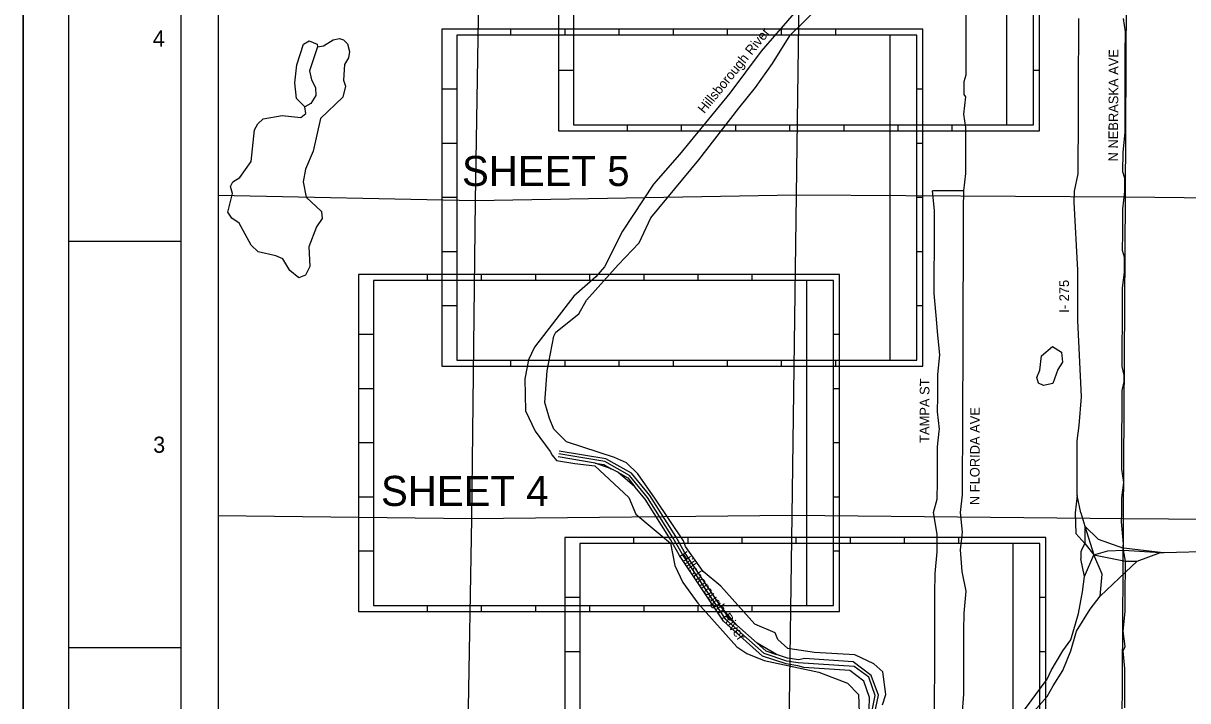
# Model space of a CAD drawing. Extents: x 492225 to 553725, y 1303773 to 1347273.
# Drawn here: x 492225 to 511586, y 1317894 to 1329150 of the extents above; entities that cross this region are included whole.
import ezdxf

# ---------------------------------------------------------------- set-up
doc = ezdxf.new("R2010")
doc.units = 0
for name, color, linetype in [('G-ANNO-TTLB', 7, 'Continuous'), ('Level 1', 7, 'Continuous'), ('Level 13', 7, 'Continuous'), ('Level 19', 7, 'Continuous'), ('Level 22', 7, 'Continuous'), ('Level 28', 7, 'Continuous'), ('Level 41', 7, 'Continuous'), ('Level 5', 7, 'Continuous'), ('Level 50', 7, 'Continuous'), ('Level 52', 7, 'Continuous'), ('Level 6', 7, 'Continuous'), ('Level 7', 7, 'Continuous')]:
    doc.layers.add(name, color=color, linetype=linetype)

msp = doc.modelspace()

# ---------------------------------------------------------------- linework, layer by layer
at = {"layer": 'G-ANNO-TTLB'}
for p, q in [((492975.069, 1346522.564), (492975.069, 1304522.564)), ((494850.069, 1305272.564), (494850.069, 1345772.564)), ((494850.069, 1325522.564), (492975.069, 1325522.564)), ((494850.069, 1318772.564), (492975.069, 1318772.564))]:
    msp.add_line(p, q, dxfattribs=at)
for points in [[(492225.069, 1303772.564), (553725.069, 1303772.564), (553725.069, 1347272.564), (492225.069, 1347272.564)], [(492225.069, 1303772.564), (553725.069, 1303772.564), (553725.069, 1347272.564), (492225.069, 1347272.564)], [(492225.069, 1347272.564), (553725.069, 1347272.564), (553725.069, 1303772.564), (492225.069, 1303772.564)]]:
    msp.add_lwpolyline(points, close=True, dxfattribs=at)
at = {"layer": 'Level 1'}
for p, q in [((508571.149, 1332863.868), (508571.149, 1327463.868)), ((499828.525, 1331625.601), (499738.271, 1326200.768)), ((505144.045, 1331549.672), (505073.326, 1326292.17)), ((510570.569, 1331572.735), (510543.414, 1326261.323)), ((500333.521, 1328952.653), (500333.521, 1329052.653)), ((501233.521, 1328952.653), (501233.521, 1329052.653)), ((502133.521, 1328952.653), (502133.521, 1329052.653)), ((503033.521, 1328952.653), (503033.521, 1329052.653)), ((503933.521, 1328952.653), (503933.521, 1329052.653)), ((504833.521, 1328952.653), (504833.521, 1329052.653)), ((505733.521, 1328952.653), (505733.521, 1329052.653)), ((506633.521, 1328952.653), (506633.521, 1323552.653)), ((501371.149, 1328363.868), (501121.149, 1328363.868)), ((509121.149, 1328363.868), (509021.149, 1328363.868)), ((499433.521, 1328052.653), (499183.521, 1328052.653)), ((507183.521, 1328052.653), (507083.521, 1328052.653)), ((502271.149, 1327363.868), (502271.149, 1327463.868)), ((503171.149, 1327363.868), (503171.149, 1327463.868)), ((504071.149, 1327363.868), (504071.149, 1327463.868)), ((504971.149, 1327363.868), (504971.149, 1327463.868)), ((505871.149, 1327363.868), (505871.149, 1327463.868)), ((506771.149, 1327363.868), (506771.149, 1327463.868)), ((507671.149, 1327363.868), (507671.149, 1327463.868)), ((499433.521, 1327152.653), (499183.521, 1327152.653)), ((507183.521, 1327152.653), (507083.521, 1327152.653)), ((499738.271, 1326200.768), (495463.793, 1326290.169)), ((499433.521, 1326252.653), (499183.521, 1326252.653)), ((499738.271, 1326200.768), (499675.349, 1320917.678)), ((505073.326, 1326292.17), (499738.271, 1326200.768)), ((505073.326, 1326292.17), (505001.79, 1320973.847)), ((510543.414, 1326261.323), (505073.326, 1326292.17)), ((507183.521, 1326252.653), (507083.521, 1326252.653)), ((510543.414, 1326261.323), (510511.962, 1320917.95)), ((515873.149, 1326207.263), (510543.414, 1326261.323)), ((499433.521, 1325352.653), (499183.521, 1325352.653)), ((507183.521, 1325352.653), (507083.521, 1325352.653)), ((498946.2, 1324877.911), (498946.2, 1324977.911)), ((499846.2, 1324877.911), (499846.2, 1324977.911)), ((500746.2, 1324877.911), (500746.2, 1324977.911)), ((501646.2, 1324877.911), (501646.2, 1324977.911)), ((502546.2, 1324877.911), (502546.2, 1324977.911)), ((503446.2, 1324877.911), (503446.2, 1324977.911)), ((504346.2, 1324877.911), (504346.2, 1324977.911)), ((505246.2, 1324877.911), (505246.2, 1319477.911)), ((499433.521, 1324452.653), (499183.521, 1324452.653)), ((507183.521, 1324452.653), (507083.521, 1324452.653)), ((498046.2, 1323977.911), (497796.2, 1323977.911)), ((505796.2, 1323977.911), (505696.2, 1323977.911)), ((500333.521, 1323452.653), (500333.521, 1323552.653)), ((501233.521, 1323452.653), (501233.521, 1323552.653)), ((502133.521, 1323452.653), (502133.521, 1323552.653)), ((503033.521, 1323452.653), (503033.521, 1323552.653)), ((503933.521, 1323452.653), (503933.521, 1323552.653)), ((504833.521, 1323452.653), (504833.521, 1323552.653)), ((505733.521, 1323452.653), (505733.521, 1323552.653)), ((498046.2, 1323077.911), (497796.2, 1323077.911)), ((505796.2, 1323077.911), (505696.2, 1323077.911)), ((498046.2, 1322177.911), (497796.2, 1322177.911)), ((505796.2, 1322177.911), (505696.2, 1322177.911)), ((498046.2, 1321277.911), (497796.2, 1321277.911)), ((505796.2, 1321277.911), (505696.2, 1321277.911)), ((499675.349, 1320917.678), (495463.793, 1320968.0574)), ((505001.79, 1320973.847), (499675.349, 1320917.678)), ((505001.79, 1320973.847), (504928.709, 1315540.774)), ((510511.962, 1320917.95), (505001.79, 1320973.847)), ((499675.349, 1320917.678), (499586.966, 1315590.825)), ((510511.962, 1320917.95), (510479.1, 1315638.587)), ((515845.848, 1320879.851), (510511.962, 1320917.95)), ((502378.147, 1320506.301), (502378.147, 1320606.301)), ((503278.147, 1320506.301), (503278.147, 1320606.301)), ((504178.147, 1320506.301), (504178.147, 1320606.301)), ((505078.147, 1320506.301), (505078.147, 1320606.301)), ((505978.147, 1320506.301), (505978.147, 1320606.301)), ((506878.147, 1320506.301), (506878.147, 1320606.301)), ((507778.147, 1320506.301), (507778.147, 1320606.301)), ((508678.147, 1320506.301), (508678.147, 1315106.301)), ((498046.2, 1320377.911), (497796.2, 1320377.911)), ((505796.2, 1320377.911), (505696.2, 1320377.911)), ((498946.2, 1319377.911), (498946.2, 1319477.911)), ((499846.2, 1319377.911), (499846.2, 1319477.911)), ((500746.2, 1319377.911), (500746.2, 1319477.911)), ((501478.147, 1319606.301), (501228.147, 1319606.301)), ((501646.2, 1319377.911), (501646.2, 1319477.911)), ((502546.2, 1319377.911), (502546.2, 1319477.911)), ((503446.2, 1319377.911), (503446.2, 1319477.911)), ((504346.2, 1319377.911), (504346.2, 1319477.911)), ((509228.147, 1319606.301), (509128.147, 1319606.301)), ((501478.147, 1318706.301), (501228.147, 1318706.301)), ((509228.147, 1318706.301), (509128.147, 1318706.301))]:
    msp.add_line(p, q, dxfattribs=at)
for points in [[(501121.149, 1327363.868), (509121.149, 1327363.868), (509121.149, 1332963.868), (501121.149, 1332963.868)], [(501371.149, 1327463.868), (509021.149, 1327463.868), (509021.149, 1332863.868), (501371.149, 1332863.868)], [(499183.521, 1323452.653), (507183.521, 1323452.653), (507183.521, 1329052.653), (499183.521, 1329052.653)], [(499433.521, 1323552.653), (507083.521, 1323552.653), (507083.521, 1328952.653), (499433.521, 1328952.653)], [(497796.2, 1319377.911), (505796.2, 1319377.911), (505796.2, 1324977.911), (497796.2, 1324977.911)], [(498046.2, 1319477.911), (505696.2, 1319477.911), (505696.2, 1324877.911), (498046.2, 1324877.911)], [(501228.147, 1315006.301), (509228.147, 1315006.301), (509228.147, 1320606.301), (501228.147, 1320606.301)], [(501478.147, 1315106.301), (509128.147, 1315106.301), (509128.147, 1320506.301), (501478.147, 1320506.301)]]:
    msp.add_lwpolyline(points, close=True, dxfattribs=at)
at = {"layer": 'Level 13'}
for p, q in [((507902.889, 1328983.074), (507904.12, 1329310.271)), ((509774.612, 1328939.736), (509775.693, 1329230.578)), ((507901.931, 1328728.588), (507902.889, 1328983.074)), ((509772.181, 1328285.343), (509774.612, 1328939.736)), ((507900.974, 1328474.102), (507901.931, 1328728.588)), ((507900.289, 1328292.325), (507900.974, 1328474.102)), ((507866.784, 1327965.25), (507867.606, 1328183.381)), ((507867.606, 1328183.381), (507900.289, 1328292.325)), ((509769.749, 1327630.95), (509772.181, 1328285.343)), ((507898.922, 1327928.773), (507866.784, 1327965.25)), ((507865.554, 1327638.053), (507898.922, 1327928.773)), ((507897.007, 1327419.801), (507865.554, 1327638.053)), ((509766.104, 1326649.36), (509769.749, 1327630.95)), ((507896.597, 1327310.735), (507897.007, 1327419.801)), ((507895.503, 1327019.894), (507896.049, 1327165.314)), ((507896.049, 1327165.314), (507896.597, 1327310.735)), ((507895.092, 1326910.828), (507895.503, 1327019.894)), ((507894.135, 1326656.343), (507895.092, 1326910.828)), ((507860.765, 1326365.623), (507894.135, 1326656.343)), ((509700.472, 1326358.758), (509766.104, 1326649.36)), ((507602.561, 1326366.592), (507344.356, 1326367.564)), ((507375.396, 1326040.246), (507344.356, 1326367.564)), ((507860.765, 1326365.623), (507602.561, 1326366.592)), ((507859.671, 1326074.781), (507860.765, 1326365.623)), ((509699.797, 1326176.983), (509700.472, 1326358.758)), ((507374.299, 1325749.405), (507375.396, 1326040.246)), ((507858.713, 1325820.295), (507859.671, 1326074.781)), ((509760.163, 1325049.734), (509699.797, 1326176.983)), ((507858.166, 1325674.874), (507858.713, 1325820.295)), ((507372.926, 1325385.853), (507374.299, 1325749.405)), ((507857.345, 1325456.743), (507858.166, 1325674.874)), ((507371.554, 1325022.302), (507372.926, 1325385.853)), ((507855.704, 1325020.482), (507855.978, 1325093.192)), ((509759.217, 1324795.248), (509760.163, 1325049.734)), ((507370.182, 1324658.75), (507371.554, 1325022.302)), ((507854.474, 1324693.285), (507855.704, 1325020.482)), ((507401.087, 1324295.077), (507370.182, 1324658.75)), ((507853.242, 1324366.089), (507854.474, 1324693.285)), ((509758.002, 1324468.053), (509759.217, 1324795.248)), ((509757.056, 1324213.566), (509758.002, 1324468.053)), ((507432.129, 1323967.759), (507401.087, 1324295.077)), ((507852.422, 1324147.958), (507853.242, 1324366.089)), ((507852.011, 1324038.893), (507852.422, 1324147.958)), ((509816.889, 1322940.899), (509757.056, 1324213.566)), ((507463.174, 1323640.442), (507432.129, 1323967.759)), ((507851.19, 1323820.763), (507852.011, 1324038.893)), ((507850.644, 1323675.342), (507851.19, 1323820.763)), ((507429.66, 1323313.368), (507463.174, 1323640.442)), ((507849.412, 1323348.145), (507849.959, 1323493.566)), ((507849.959, 1323493.566), (507850.644, 1323675.342)), ((507428.289, 1322949.816), (507429.66, 1323313.368)), ((507848.319, 1323057.304), (507849.412, 1323348.145)), ((507427.329, 1322695.331), (507428.289, 1322949.816)), ((507847.224, 1322766.463), (507847.908, 1322948.239)), ((507847.908, 1322948.239), (507848.319, 1323057.304)), ((509782.855, 1322468.402), (509816.889, 1322940.899)), ((507846.13, 1322475.623), (507847.224, 1322766.463)), ((507458.511, 1322404.368), (507427.329, 1322695.331)), ((507425.135, 1322113.649), (507454.839, 1322372.388)), ((507454.839, 1322372.388), (507458.511, 1322404.368)), ((507844.9, 1322148.427), (507846.13, 1322475.623)), ((507843.532, 1321784.876), (507844.9, 1322148.427)), ((507423.764, 1321750.098), (507425.135, 1322113.649)), ((507422.941, 1321531.968), (507423.764, 1321750.098)), ((507842.849, 1321603.1), (507843.532, 1321784.876)), ((507841.754, 1321312.26), (507842.849, 1321603.1)), ((507421.844, 1321241.126), (507422.941, 1321531.968)), ((507356.461, 1321023.238), (507421.844, 1321241.126)), ((507808.381, 1321021.54), (507841.754, 1321312.26)), ((509746.257, 1321305.158), (509712.897, 1321014.438)), ((509809.738, 1321014.078), (509746.257, 1321305.158)), ((507419.65, 1320659.444), (507356.461, 1321023.238)), ((507839.43, 1320694.223), (507808.381, 1321021.54)), ((509712.897, 1321014.438), (509725.826, 1320671.193)), ((509809.738, 1321014.078), (509873.488, 1320795.709)), ((509873.488, 1320795.709), (509872.409, 1320504.869)), ((509873.488, 1320795.709), (510024.072, 1320315.258)), ((507418.553, 1320368.604), (507419.65, 1320659.444)), ((507806.055, 1320403.503), (507839.43, 1320694.223)), ((509725.826, 1320671.193), (509872.409, 1320504.869)), ((507836.969, 1320039.832), (507806.055, 1320403.503)), ((509872.409, 1320504.869), (510024.072, 1320315.258)), ((510517.614, 1320393.42), (511130.808, 1320354.81)), ((511130.808, 1320354.81), (510517.747, 1320429.775)), ((511192.147, 1320356.403), (512389.879, 1320386.567)), ((507384.901, 1320005.174), (507418.553, 1320368.604)), ((509870.387, 1319959.543), (509806.904, 1320250.623)), ((509870.387, 1319959.543), (510024.072, 1320315.258)), ((510024.072, 1320315.258), (510549.223, 1320211.525)), ((510548.551, 1320029.75), (510742.906, 1320210.813)), ((510549.223, 1320211.525), (510742.906, 1320210.813)), ((510742.906, 1320210.813), (511130.808, 1320354.81)), ((511130.808, 1320354.81), (511192.147, 1320356.403)), ((507383.668, 1319677.979), (507384.901, 1320005.174)), ((507900.3, 1319712.393), (507836.969, 1320039.832)), ((510127.421, 1319631.393), (510548.551, 1320029.75)), ((509837.161, 1319705.178), (509870.387, 1319959.543)), ((507382.433, 1319350.783), (507383.668, 1319677.979)), ((507866.653, 1319348.964), (507900.3, 1319712.393)), ((509771.25, 1319341.866), (509837.161, 1319705.178)), ((509965.208, 1319413.859), (510127.421, 1319631.393)), ((507381.199, 1319023.588), (507382.433, 1319350.783)), ((507865.559, 1319058.124), (507866.653, 1319348.964)), ((509640.504, 1318906.083), (509771.25, 1319341.866)), ((509737.889, 1319051.145), (509965.208, 1319413.859)), ((507864.329, 1318730.928), (507865.559, 1319058.124)), ((509639.829, 1318724.308), (509737.889, 1319051.145)), ((507379.965, 1318696.393), (507381.199, 1319023.588)), ((509510.703, 1318724.788), (509640.504, 1318906.083)), ((507378.73, 1318369.197), (507379.965, 1318696.393)), ((507863.099, 1318403.733), (507864.329, 1318730.928)), ((509315.678, 1318397.817), (509510.703, 1318724.788)), ((509509.485, 1318397.592), (509639.829, 1318724.308)), ((507377.223, 1317969.292), (507378.73, 1318369.197)), ((507861.596, 1318003.828), (507863.099, 1318403.733)), ((509250.688, 1318253.13), (509315.678, 1318397.817)), ((509347.129, 1318143.706), (509509.485, 1318397.592)), ((508796.428, 1317636.777), (509250.688, 1318253.13)), ((509249.605, 1317962.29), (509347.129, 1318143.706)), ((507375.852, 1317605.741), (507377.223, 1317969.292)), ((507827.674, 1317567.688), (507861.596, 1318003.828)), ((508860.586, 1317527.471), (509249.605, 1317962.29))]:
    msp.add_line(p, q, dxfattribs=at)
for points in [[(507855.978, 1325093.192), (507856.388, 1325202.258), (507857.345, 1325456.743)], [(509746.257, 1321305.158), (509749.631, 1322214.036), (509782.855, 1322468.402)], [(509873.488, 1320795.709), (510098.64, 1320576.744), (510517.747, 1320429.775)], [(509872.409, 1320504.869), (509833.36, 1320420.669), (509807.341, 1320368.413), (509806.904, 1320250.623)], [(510024.072, 1320315.258), (510256.749, 1320384.203), (510517.614, 1320393.42)], [(510127.421, 1319631.393), (510161.048, 1319994.823), (510024.072, 1320315.258)]]:
    msp.add_lwpolyline(points, dxfattribs=at)
at = {"layer": 'Level 22'}
for p, q in [((510549.443, 1329009.583), (510517.976, 1329227.833)), ((510548.099, 1328646.031), (510549.443, 1329009.583)), ((510547.025, 1328355.19), (510548.099, 1328646.031)), ((510545.682, 1327991.638), (510547.025, 1328355.19)), ((510544.472, 1327664.442), (510545.682, 1327991.638)), ((510543.264, 1327337.246), (510544.472, 1327664.442)), ((510509.779, 1327010.168), (510543.264, 1327337.246)), ((510508.569, 1326682.972), (510509.779, 1327010.168)), ((510540.443, 1326573.787), (510508.569, 1326682.972)), ((510539.636, 1326355.656), (510540.443, 1326573.787)), ((510506.286, 1326064.934), (510539.636, 1326355.656)), ((510504.809, 1325665.028), (510506.286, 1326064.934)), ((510503.734, 1325374.187), (510504.809, 1325665.028)), ((510535.607, 1325265.003), (510503.734, 1325374.187)), ((510534.667, 1325010.516), (510535.607, 1325265.003)), ((510501.45, 1324756.149), (510534.667, 1325010.516)), ((510500.375, 1324465.308), (510501.45, 1324756.149)), ((510499.837, 1324319.888), (510500.375, 1324465.308)), ((510499.3, 1324174.468), (510499.837, 1324319.888)), ((510497.823, 1323774.561), (510499.3, 1324174.468)), ((510496.614, 1323447.366), (510497.554, 1323701.851)), ((510497.554, 1323701.851), (510497.823, 1323774.561)), ((510528.354, 1323301.826), (510496.614, 1323447.366)), ((510527.952, 1323192.761), (510528.354, 1323301.826)), ((510495.136, 1323047.459), (510527.952, 1323192.761)), ((510494.062, 1322756.618), (510495.136, 1323047.459)), ((510493.256, 1322538.488), (510494.062, 1322756.618)), ((510492.987, 1322465.778), (510493.256, 1322538.488)), ((510492.048, 1322211.293), (510492.585, 1322356.713)), ((510492.585, 1322356.713), (510492.987, 1322465.778)), ((510491.644, 1322102.227), (510492.048, 1322211.293)), ((510490.302, 1321738.677), (510491.375, 1322029.517)), ((510491.375, 1322029.517), (510491.644, 1322102.227)), ((510521.775, 1321520.427), (510490.302, 1321738.677)), ((510488.556, 1321266.06), (510521.775, 1321520.427)), ((510487.615, 1321011.575), (510488.556, 1321266.06)), ((510487.079, 1320866.155), (510487.615, 1321011.575)), ((510518.016, 1320502.485), (510487.079, 1320866.155)), ((510517.614, 1320393.42), (510517.747, 1320429.775)), ((510549.223, 1320211.525), (510517.614, 1320393.42)), ((510517.747, 1320429.775), (510518.016, 1320502.485)), ((510548.551, 1320029.75), (510549.223, 1320211.525)), ((510547.612, 1319775.265), (510548.551, 1320029.75)), ((510546.136, 1319375.36), (510547.612, 1319775.265)), ((510512.646, 1319048.283), (510546.136, 1319375.36)), ((510543.989, 1318793.679), (510512.646, 1319048.283)), ((510511.438, 1318721.088), (510543.989, 1318793.679)), ((510542.647, 1318430.128), (510511.438, 1318721.088)), ((510541.439, 1318102.933), (510542.647, 1318430.128)), ((510540.231, 1317775.738), (510541.439, 1318102.933))]:
    msp.add_line(p, q, dxfattribs=at)
at = {"layer": 'Level 5'}
for points in [[(505552.993, 1329911.152), (504490.919, 1328689.166), (503972.092, 1327990.618), (503137.059, 1326968.639), (502700.78, 1326477.548), (502190.064, 1325695.649), (501888.265, 1325104.804), (501746.066, 1324938.562), (501378.398, 1324614.597), (500725.802, 1323766.447), (500625.163, 1323558.405), (500565.904, 1323241.863), (500572.634, 1322708.441), (500738.324, 1322374.582), (500985.158, 1322032.033), (501020.664, 1321975.498), (501090.771, 1321884.691), (501394.409, 1321835.17), (501726.68, 1321794.098), (502293.509, 1321269.853), (502409.389, 1320994.453), (502987.719, 1320510.528), (503056.908, 1320142.416), (503189.398, 1319858.687), (503438.398, 1319516.218), (504086.306, 1318789.201), (504252.675, 1318680.353), (504544.024, 1318562.805), (505451.881, 1318368.413), (505926.36, 1318183.658), (506109.189, 1317999.758), (506132.38, 1317399.596)], [(506508.689, 1317823.542), (506567.558, 1317998.363), (506518.687, 1318373.574), (506369.048, 1318507.373), (506052.809, 1318658.32), (505377.851, 1318693.674), (504936.323, 1318761.649), (504770.074, 1318912.178), (504728.724, 1319020.648), (504387.454, 1319163.346), (503822.625, 1319798.443), (503531.656, 1320041.011), (503232.857, 1320458.599), (503199.817, 1320550.369), (502737.677, 1321243.657), (502440.64, 1321661.495), (502255.817, 1321845.074), (502052.886, 1321934.213), (501254.502, 1322198.046), (501046.793, 1322407.005), (500972.313, 1322582.234), (500898.103, 1322849.155), (500932.982, 1323374.128), (501045.365, 1323950.382), (501078.471, 1324015.119), (501460.889, 1324322.677), (501588.125, 1324548.903), (502116.42, 1325135.621), (502464.503, 1325503.162), (502657.451, 1325919.305), (503454.477, 1326880.052), (504121.372, 1327740.168), (504397.43, 1328081.033), (504681.959, 1328480.237), (504975.097, 1328954.432), (505668.853, 1329635.782)], [(496906.391, 1327759.297), (496765.112, 1327901.396), (496740.911, 1328159.837), (496775.141, 1328459.758), (496884.5, 1328801.161), (496976.359, 1328859.242), (497109.499, 1328800.483), (497117.719, 1328758.813)], [(497117.719, 1328758.813), (496983.18, 1328359.16), (497016.07, 1328209.05), (497082.36, 1328083.82), (497090.31, 1327950.47), (497006.581, 1327817.348), (496906.391, 1327759.297)]]:
    msp.add_lwpolyline(points, dxfattribs=at)
msp.add_lwpolyline([(509185.954, 1323129.979), (509102.754, 1323171.888), (509078.014, 1323263.628), (509128.374, 1323388.499), (509154.093, 1323621.781), (509337.902, 1323779.613), (509487.662, 1323687.484), (509503.822, 1323520.734), (509428.463, 1323395.943), (509344.393, 1323162.841), (509185.954, 1323129.979)], close=True, dxfattribs=at)
at = {"layer": 'Level 50'}
for p, q in [((501735.873, 1321841.427), (501119.377, 1321944.185)), ((501908.806, 1321913.984), (501135.819, 1322042.825)), ((501998.798, 1321749.444), (501735.873, 1321841.427)), ((501735.873, 1321841.427), (501875.296, 1321818.188)), ((501875.296, 1321818.188), (501998.798, 1321749.444)), ((502339.715, 1321674.131), (501908.806, 1321913.984)), ((502107.982, 1321688.67), (501998.798, 1321749.444)), ((502394.936, 1321448.604), (502107.982, 1321688.67)), ((502107.982, 1321688.67), (502274.391, 1321596.043)), ((502274.391, 1321596.043), (502394.936, 1321448.604)), ((502644.251, 1321301.65), (502339.715, 1321674.131)), ((502562.953, 1321243.102), (502394.936, 1321448.604)), ((502987.586, 1320570.113), (502562.953, 1321243.102)), ((503073.418, 1320621.479), (502644.251, 1321301.65)), ((503221.013, 1320361.041), (503073.418, 1320621.479)), ((503135.831, 1320308.531), (502987.586, 1320570.113)), ((503867.146, 1319212.946), (503135.831, 1320308.531)), ((503835.732, 1319440.131), (503221.013, 1320361.041)), ((504087.796, 1319150.359), (503835.732, 1319440.131)), ((503835.732, 1319440.131), (503943.218, 1319279.106)), ((503943.218, 1319279.106), (504087.796, 1319150.359)), ((504517.919, 1318633.431), (503867.146, 1319212.946)), ((504427.352, 1318847.983), (504087.796, 1319150.359)), ((504749.031, 1318662.11), (504427.352, 1318847.983)), ((504427.352, 1318847.983), (504569.004, 1318721.841)), ((504569.004, 1318721.841), (504749.031, 1318662.11)), ((504930.875, 1318601.776), (504749.031, 1318662.11)), ((504907.849, 1318504.056), (504517.919, 1318633.431)), ((505102.948, 1318476.053), (504907.849, 1318504.056)), ((505117.156, 1318575.039), (504930.875, 1318601.776)), ((505204.848, 1318444.069), (505102.948, 1318476.053)), ((505214.814, 1318593.737), (505117.156, 1318575.039)), ((506021.952, 1318539.996), (505214.814, 1318593.737)), ((506324.045, 1318314.052), (506021.952, 1318539.996)), ((505967.673, 1318393.278), (505204.848, 1318444.069)), ((506198.126, 1318220.915), (505967.673, 1318393.278)), ((506442.022, 1317985.784), (506324.045, 1318314.052)), ((506296.126, 1317948.234), (506198.126, 1318220.915)), ((505969.074, 1315668.009), (506442.022, 1317985.784)), ((506291.259, 1317747.1), (506296.126, 1317948.234))]:
    msp.add_line(p, q, dxfattribs=at)
at = {"layer": 'Level 52'}
msp.add_lwpolyline([(518939.5614, 1342691.8404), (495463.7934, 1342691.8404), (495463.7934, 1307817.676), (518939.5614, 1307817.676)], close=True, dxfattribs=at)
at = {"layer": 'Level 6'}
for p, q in [((501892.052, 1321866.086), (501127.598, 1321993.505)), ((502307.052, 1321635.088), (501892.052, 1321866.086)), ((502603.602, 1321272.376), (502307.052, 1321635.088)), ((503030.502, 1320595.796), (502603.602, 1321272.376)), ((503178.422, 1320334.786), (503030.502, 1320595.796)), ((503905.182, 1319246.026), (503178.422, 1320334.786)), ((504543.462, 1318677.636), (503905.182, 1319246.026)), ((504919.362, 1318552.916), (504543.462, 1318677.636)), ((505110.052, 1318525.546), (504919.362, 1318552.916)), ((506040.632, 1318463.586), (505110.052, 1318525.546)), ((506282.072, 1318283.006), (506040.632, 1318463.586)), ((506390.232, 1317982.056), (506282.072, 1318283.006)), ((505918.062, 1315668.096), (506390.232, 1317982.056))]:
    msp.add_line(p, q, dxfattribs=at)
at = {"layer": 'Level 7'}
msp.add_lwpolyline([(497117.719, 1328758.813), (497217.789, 1328775.154), (497376.408, 1328874.696), (497484.857, 1328899.368), (497551.437, 1328874.188), (497617.907, 1328807.308), (497650.897, 1328682.198), (497633.897, 1328573.908), (497566.898, 1328465.767), (497549.458, 1328207.446), (497582.498, 1328107.346), (497540.289, 1327924.104), (497164.17, 1327566.869), (497045.882, 1327025.466), (496919.973, 1326725.833), (496877.683, 1326517.583), (496926.914, 1326259.092), (497184.573, 1326024.953), (497192.553, 1325908.233), (497100.453, 1325766.842), (496974.464, 1325433.839), (496990.154, 1325108.758), (496914.725, 1324967.307), (496806.225, 1324917.626), (496656.586, 1325043.094), (496540.496, 1325235.114), (496423.967, 1325285.473), (496132.458, 1325353.01), (496016.098, 1325461.689), (495817.169, 1325828.998), (495692.419, 1325912.698), (495626.039, 1326012.928), (495701.968, 1326321.069), (495668.988, 1326437.849), (495710.868, 1326512.74), (495827.787, 1326587.392), (496011.916, 1326853.544), (496071.835, 1327378.417), (496122.135, 1327478.288), (496214.054, 1327561.339), (496530.913, 1327618.733), (496839.172, 1327584.476), (496922.731, 1327650.917), (496906.391, 1327759.297)], dxfattribs=at)

# ---------------------------------------------------------------- texts
at = {"layer": 'G-ANNO-TTLB'}
for s, p in [('4', (494379.069, 1328764.064)), ('3', (494385.069, 1322014.064))]:
    msp.add_text(s, height=267.507, dxfattribs=at).set_placement(p)
at = {"layer": 'Level 1'}
for s, p in [('SHEET 5', (499519.214, 1326446.087)), ('SHEET 4', (498172.422, 1321130.115))]:
    msp.add_text(s, height=500, dxfattribs=at).set_placement(p)
at = {"layer": 'Level 19'}
for s, height, rotation, p in [('I- 275', 160, 89.78710834, (509609.561, 1324339.452)), ('TAMPA ST', 160, 89.78378888, (507287.909, 1322178.181)), ('N FLORIDA AVE', 159.999996, 89.78438889, (508123.08, 1321143.532))]:
    msp.add_text(s, height=height, rotation=rotation, dxfattribs=at).set_placement(p)
at = {"layer": 'Level 28'}
msp.add_text('N NEBRASKA AVE', height=159.999996, rotation=89.78817778, dxfattribs=at).set_placement((510426.362, 1326854.36))
at = {"layer": 'Level 41'}
for rotation, p in [(50.90274999, (503547.824, 1327639.364)), (305.01855279, (503116.958, 1320305.125))]:
    msp.add_text('Hillsborough River', height=159.999996, rotation=rotation, dxfattribs=at).set_placement(p)

doc.saveas('drawing.dxf')
